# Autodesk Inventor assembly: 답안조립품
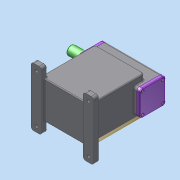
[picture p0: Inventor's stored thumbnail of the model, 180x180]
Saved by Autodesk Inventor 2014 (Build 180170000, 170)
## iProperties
Created: 2025-06
Part Number: 답안조립품
Document SubType Name: Assembly
Designer: dg
Author: dg
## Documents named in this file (13)
- C:\Users\dg\Desktop\750603V1012\답안조립품.iam
- C:\Users\dg\Desktop\750603V1012\본체.ipt
- C:\Users\dg\Desktop\750603V1012\가져온 구성요소\깊은 홈 볼 베어링 6206\깊은 홈 볼 베어링 6206.ipt
- C:\Users\dg\Desktop\750603V1012\가져온 구성요소\뒷커버\뒷커버.ipt
- C:\Users\dg\Desktop\750603V1012\가져온 구성요소\6각 구멍붙이 볼트 M6x12\6각 구멍붙이 볼트 M6x12.ipt
- C:\Users\dg\Desktop\750603V1012\가져온 구성요소\웜 샤프트\웜 샤프트.ipt
- C:\Users\dg\Desktop\750603V1012\가져온 구성요소\앞커버\앞커버.ipt
- C:\Users\dg\Desktop\750603V1012\가져온 구성요소\오일 실 35 55 11\오일 실 35 55 11.ipt
- C:\Users\dg\Desktop\750603V1012\가져온 구성요소\깊은 홈 볼 베어링 6209\깊은 홈 볼 베어링 6209.ipt
- C:\Users\dg\Desktop\750603V1012\가져온 구성요소\웜 휠\웜 휠.ipt
- C:\Users\dg\Desktop\750603V1012\가져온 구성요소\웜 휠 커버\웜 휠 커버.ipt
- C:\Users\dg\Desktop\750603V1012\가져온 구성요소\6각 구멍붙이 볼트 M8x20\6각 구멍붙이 볼트 M8x20.ipt
- C:\Users\dg\Desktop\750603V1012\가져온 구성요소\오일 실 30 42 7\오일 실 30 42 7.ipt
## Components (12 placed, 2 different names)
1. 6각 구멍붙이 볼트 M8x20:1
2. 6각 구멍붙이 볼트 M8x20:2
3. 6각 구멍붙이 볼트 M8x20:3
4. 6각 구멍붙이 볼트 M8x20:4
5. 6각 구멍붙이 볼트 M6x12:1
6. 6각 구멍붙이 볼트 M6x12:2
7. 6각 구멍붙이 볼트 M6x12:3
8. 6각 구멍붙이 볼트 M6x12:4
9. 6각 구멍붙이 볼트 M6x12:5
10. 6각 구멍붙이 볼트 M6x12:6
11. 6각 구멍붙이 볼트 M6x12:7
12. 6각 구멍붙이 볼트 M6x12:8
